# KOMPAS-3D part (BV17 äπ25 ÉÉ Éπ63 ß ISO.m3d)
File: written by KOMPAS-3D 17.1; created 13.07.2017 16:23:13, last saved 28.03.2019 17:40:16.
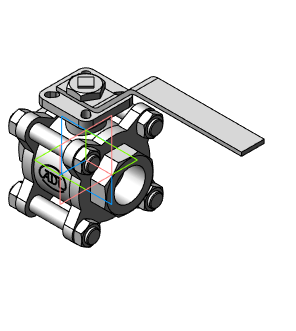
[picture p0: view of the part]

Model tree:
1. Операция без истории:2  (labels: Сталь 20  ГОСТ 1050-88)

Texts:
  DISO1
  DISO2
  BV17 Ду8 1/4" Ру63 с ISO
  BV17 Ду8 СС Ру63 с ISO
  BV17 Ду10 3/8" Ру63 с ISO
  BV17 Ду10 СС Ру63 с ISO
  BV17 Ду15 1/2" Ру63 с ISO
  BV17 Ду15 СС Ру63 с ISO
  BV17 Ду15 ФФ Ру40 с ISO
  BV17 Ду20 3/4" Ру63 с ISO
  BV17 Ду20 СС Ру40 с ISO
  BV17 Ду20 ФФ Ру40 с ISO
  BV17 Ду25 1" Ру63 с ISO
  BV17 Ду25 СС Ру63 с ISO
  BV17 Ду25 ФФ Ру40 с ISO
  BV17 Ду32 1 1/4" Ру63 с ISO
  BV17 Ду32 СС Ру63 с ISO
  BV17 Ду32 ФФ Ру40 с ISO
  BV17 Ду40 1 1/2" Ру63 с ISO
  BV17 Ду40 СС Ру63 с ISO
  BV17 Ду40 ФФ Ру40 с ISO
  BV17 Ду50 2" Ру63 с ISO
  BV17 Ду50 СС Ру63 с ISO
  BV17 Ду50 ФФ Ру40 с ISO
  BV17 Ду65 2 1/2" Ру40 с ISO
  BV17 Ду65 СС Ру40 с ISO
  BV17 Ду65 ФФ Ру40 с ISO
  BV17 Ду80 3" Ру40 с ISO
  BV17 Ду80 СС Ру40 с ISO
  BV17 Ду80 ФФ Ру40 с ISO
  BV17 Ду100 4" Ру40 с ISO
  BV17 Ду100 СС Ру40 с ISO
  BV17 Ду100 ФФ Ру40 с ISO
